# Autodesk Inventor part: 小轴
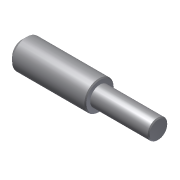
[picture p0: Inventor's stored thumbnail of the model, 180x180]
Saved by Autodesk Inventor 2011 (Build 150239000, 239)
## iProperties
Created: 2012-10
Part Number: 小轴
Document SubType Name: Modeling
Designer: Administrator
Density: 1 g/cm^3
Author: Administrator
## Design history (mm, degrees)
sketch "草图1"
  geometry: L1 (0, 0)-(0, 3); L2 (0, 3)-(16, 3); L3 (16, 3)-(16, 2); L4 (16, 2)-(28, 2); L5 (28, 2)-(28, 0); L6 (28, 0)-(0, 0)
  constraints: 12 end point, 4 parallel, 1 perpendicular, 1 vertical
  dimensions: "d0" = 16 distance of L1.end L2.end; "d2" = 6 diameter of L2 L6; "d3" = 28 distance between parallel lines of L5 L1; "d4" = 4 diameter of L4 L6
revolve "旋转1" sketch "草图1" stored, may be unused: angle "d5" = 90 deg
chamfer "倒角1" distance "d6" = 1; stored, may be unused: second distance "d7" = 2, angle "d8" = 45 deg
chamfer "倒角2" distance "d9" = 0.2; stored, may be unused: second distance "d10" = 2, angle "d11" = 45 deg
chamfer "倒角3" distance "d12" = 0.2; stored, may be unused: second distance "d13" = 2, angle "d14" = 45 deg
node "实体1"
